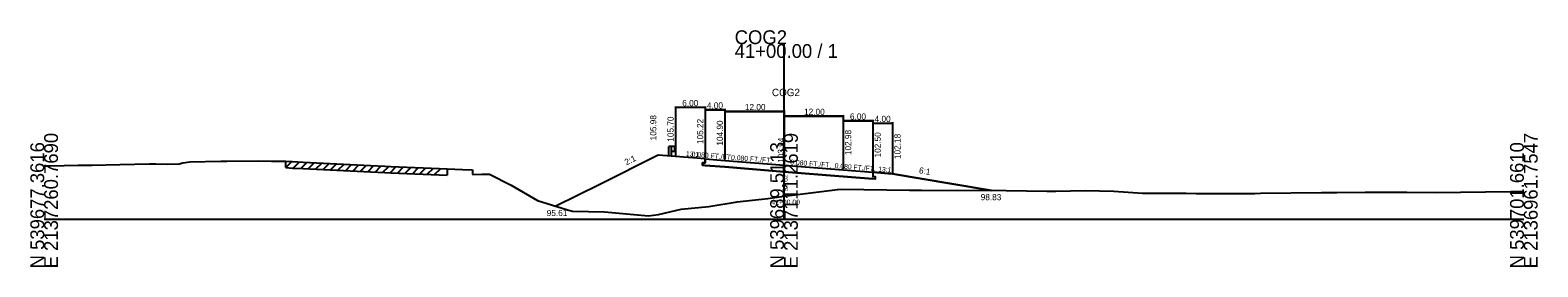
# Model space of a CAD drawing. Extents: x -13397 to 2303, y -10 to 39059.
# Drawn here: x 997.2 to 1302.8, y 21990.3 to 22038.3 of the extents above; entities that cross this region are included whole.
import ezdxf

# ---------------------------------------------------------------- set-up
doc = ezdxf.new("R2010")
doc.units = 0
for name, color, linetype in [('Level 1', 7, 'Continuous'), ('Level 5', 7, 'Continuous'), ('Level 53', 7, 'Continuous'), ('Level 54', 7, 'Continuous'), ('Level 55', 7, 'Continuous'), ('Level 7', 7, 'Continuous'), ('RD_GPK_XS_Cell', 7, 'Continuous'), ('RD_XS_EwShp', 7, 'Continuous'), ('RD_XS_ExGround', 7, 'Continuous'), ('RD_XS_ExPaveRet', 7, 'Continuous'), ('RD_XS_Pave', 7, 'Continuous'), ('RD_XS_TX_Baseline', 7, 'Continuous'), ('RD_XS_TX_Elev_EX', 7, 'Continuous'), ('RD_XS_TX_Elev_PR', 7, 'Continuous'), ('RD_XS_TX_Station', 7, 'Continuous')]:
    doc.layers.add(name, color=color, linetype=linetype)

msp = doc.modelspace()

# ---------------------------------------------------------------- linework, layer by layer
at = {"layer": 'Level 1'}
for p, q in [((1126.66, 22012.7), (1126.66, 22014.69)), ((1127.22, 22014.69), (1126.66, 22014.69)), ((1127.22, 22012.7), (1127.22, 22014.69)), ((1127.77, 22014.69), (1127.22, 22014.69)), ((1127.77, 22013.72), (1127.22, 22013.72)), ((1127.77, 22014.69), (1127.77, 22013.72)), ((1127.85, 22014.61), (1127.77, 22014.63)), ((1127.85, 22013.79), (1127.77, 22013.78)), ((1127.84, 22014.28), (1127.84, 22014.12)), ((1127.98, 22014.52), (1127.86, 22014.61)), ((1127.98, 22014.42), (1127.86, 22014.32)), ((1127.98, 22013.99), (1127.86, 22014.08)), ((1127.98, 22013.89), (1127.86, 22013.79))]:
    msp.add_line(p, q, dxfattribs=at)
for centre, radius, start, end in [((1127.91, 22014.28), 0.0651, 135, 180), ((1127.91, 22014.12), 0.0651, 180, 237.0105), ((1127.85, 22014.59), 0.026, 50.9495, 90), ((1127.85, 22013.81), 0.026, 270, 309.0504), ((1127.93, 22014.47), 0.0651, 309.0337, 50.9664), ((1127.93, 22013.94), 0.0651, 309.0337, 50.9664)]:
    msp.add_arc(centre, radius, start, end, dxfattribs=at)
at = {"layer": 'Level 5'}
for p, q in [((1134, 22012.22), (1134, 22011.39)), ((1133.5, 22011.43), (1133.5, 22010.93)), ((1134, 22011.39), (1133.5, 22011.43)), ((1133.5, 22010.93), (1134, 22010.89)), ((1138, 22010.57), (1134, 22010.89)), ((1138, 22010.57), (1134, 22010.89)), ((1138, 22010.57), (1134, 22010.89)), ((1134, 22010.89), (1138, 22010.57)), ((1150, 22009.61), (1138, 22010.57)), ((1150, 22009.61), (1138, 22010.57)), ((1150, 22009.61), (1138, 22010.57)), ((1138, 22010.57), (1150, 22009.61)), ((1138, 22010.57), (1150, 22009.61)), ((1162, 22008.65), (1150, 22009.61)), ((1162, 22008.65), (1150, 22009.61)), ((1150, 22009.61), (1162, 22008.65)), ((1150, 22009.61), (1162, 22008.65)), ((1150, 22009.61), (1162, 22008.65)), ((1168, 22009.5), (1168, 22008.67)), ((1168, 22008.17), (1162, 22008.65)), ((1162, 22008.65), (1168, 22008.17)), ((1162, 22008.65), (1168, 22008.17)), ((1162, 22008.65), (1168, 22008.17)), ((1168, 22008.67), (1168.5, 22008.63)), ((1168.5, 22008.13), (1168, 22008.17)), ((1168.5, 22008.63), (1168.5, 22008.13))]:
    msp.add_line(p, q, dxfattribs=at)
at = {"layer": 'Level 54'}
for p, q in [((1128, 22022.85), (1128, 22012.9)), ((1134, 22022.65), (1128, 22022.65)), ((1134, 22022.85), (1134, 22012.42)), ((1134, 22022.37), (1134, 22012.42)), ((1134, 22022.37), (1134, 22012.42)), ((1134, 22022.37), (1134, 22012.42)), ((1134, 22022.37), (1134, 22012.42)), ((1134, 22022.17), (1138, 22022.17)), ((1134, 22022.17), (1138, 22022.17)), ((1134, 22022.17), (1138, 22022.17)), ((1138, 22022.17), (1134, 22022.17)), ((1138, 22022.37), (1138, 22012.1)), ((1138, 22022.37), (1138, 22012.1)), ((1138, 22022.37), (1138, 22012.1)), ((1138, 22022.37), (1138, 22012.1)), ((1138, 22022.05), (1138, 22012.1)), ((1138, 22022.05), (1138, 22012.1)), ((1138, 22022.05), (1138, 22012.1)), ((1138, 22022.05), (1138, 22012.1)), ((1138, 22022.05), (1138, 22012.1)), ((1138, 22021.85), (1150, 22021.85)), ((1138, 22021.85), (1150, 22021.85)), ((1138, 22021.85), (1150, 22021.85)), ((1150, 22021.85), (1138, 22021.85)), ((1150, 22021.85), (1138, 22021.85)), ((1150, 22022.05), (1150, 22011.14)), ((1150, 22022.05), (1150, 22011.14)), ((1150, 22022.05), (1150, 22011.14)), ((1150, 22022.05), (1150, 22011.14)), ((1150, 22022.05), (1150, 22011.14)), ((1150, 22021.09), (1150, 22011.14)), ((1150, 22021.09), (1150, 22011.14)), ((1150, 22021.09), (1150, 22011.14)), ((1150, 22021.09), (1150, 22011.14)), ((1150, 22021.09), (1150, 22011.14)), ((1150, 22020.89), (1162, 22020.89)), ((1150, 22020.89), (1162, 22020.89)), ((1162, 22020.89), (1150, 22020.89)), ((1162, 22020.89), (1150, 22020.89)), ((1162, 22020.89), (1150, 22020.89)), ((1162, 22021.09), (1162, 22010.18)), ((1162, 22021.09), (1162, 22010.18)), ((1162, 22021.09), (1162, 22010.18)), ((1162, 22021.09), (1162, 22010.18)), ((1162, 22021.09), (1162, 22010.18)), ((1162, 22020.13), (1162, 22010.18)), ((1162, 22020.13), (1162, 22010.18)), ((1162, 22020.13), (1162, 22010.18)), ((1162, 22020.13), (1162, 22010.18)), ((1162, 22019.93), (1168, 22019.93)), ((1168, 22019.93), (1162, 22019.93)), ((1168, 22019.93), (1162, 22019.93)), ((1168, 22019.93), (1162, 22019.93)), ((1168, 22020.13), (1168, 22009.7)), ((1168, 22020.13), (1168, 22009.7)), ((1168, 22020.13), (1168, 22009.7)), ((1168, 22020.13), (1168, 22009.7)), ((1168, 22019.65), (1168, 22009.7)), ((1168, 22019.45), (1172, 22019.45)), ((1172, 22019.65), (1172, 22009.38))]:
    msp.add_line(p, q, dxfattribs=at)
at = {"layer": 'Level 7'}
for p, q in [((1124.5, 22012.98), (1112.5, 22006.98)), ((1128, 22012.7), (1124.5, 22012.98)), ((1134, 22012.22), (1128, 22012.7)), ((1168, 22009.5), (1172, 22009.18)), ((1172, 22009.18), (1184, 22007.18)), ((1112.5, 22006.98), (1103.77, 22002.61)), ((1184, 22007.18), (1192.08, 22005.83))]:
    msp.add_line(p, q, dxfattribs=at)
at = {"layer": 'RD_GPK_XS_Cell'}
for p, q in [((1150, 22000), (1150, 22035.49)), ((1000, 22000), (1150, 22000)), ((1150, 22000), (1300, 22000))]:
    msp.add_line(p, q, dxfattribs=at)
at = {"layer": 'RD_XS_EwShp'}
msp.add_lwpolyline([(1134, 22012.22), (1128, 22012.7), (1124.5, 22012.98), (1112.5, 22006.98), (1103.77, 22002.61), (1106.13, 22001.88), (1107.15, 22001.59), (1113.62, 22001.45), (1122.54, 22000.68), (1124.54, 22000.92), (1129.13, 22001.99), (1134.73, 22002.58), (1140.51, 22003.49), (1146.73, 22004.19), (1148.16, 22004.39), (1150, 22004.62), (1160.83, 22005.99), (1161.58, 22006.04), (1175.46, 22005.84), (1176.05, 22005.87), (1176.64, 22005.85), (1177.86, 22005.86), (1192.08, 22005.83), (1184, 22007.18), (1172, 22009.18), (1168, 22009.5), (1168, 22008.67), (1168.5, 22008.63), (1168.5, 22008.13), (1168, 22008.17), (1162, 22008.65), (1150, 22009.61), (1138, 22010.57), (1134, 22010.89), (1133.5, 22010.93), (1133.5, 22011.43), (1134, 22011.39)], close=True, dxfattribs=at)
at = {"layer": 'RD_XS_ExGround'}
for p, q in [((1000, 22010.79), (1001.19, 22010.82)), ((1001.19, 22010.82), (1006.9, 22010.91)), ((1006.9, 22010.91), (1008.29, 22010.93)), ((1008.29, 22010.93), (1009.7, 22010.96)), ((1009.7, 22010.96), (1015.33, 22011.05)), ((1015.33, 22011.05), (1021.36, 22011.21)), ((1021.36, 22011.21), (1022.65, 22011.23)), ((1022.65, 22011.23), (1025.05, 22011.17)), ((1025.05, 22011.17), (1027.36, 22011.18)), ((1027.36, 22011.18), (1028.13, 22011.39)), ((1028.13, 22011.39), (1029.51, 22011.63)), ((1029.51, 22011.63), (1035.83, 22011.76)), ((1035.83, 22011.76), (1037.06, 22011.77)), ((1037.06, 22011.77), (1043.55, 22011.83)), ((1043.55, 22011.83), (1046.1, 22011.78)), ((1046.1, 22011.78), (1049, 22011.73)), ((1049, 22011.73), (1050.34, 22011.65)), ((1050.34, 22011.65), (1052.49, 22011.54)), ((1052.49, 22011.54), (1066.18, 22010.87)), ((1066.18, 22010.87), (1069.08, 22010.73)), ((1069.08, 22010.73), (1070.28, 22010.69)), ((1070.28, 22010.69), (1081.73, 22010.22)), ((1081.73, 22010.22), (1084.81, 22010.08)), ((1084.81, 22010.08), (1086.84, 22010.01)), ((1086.84, 22010.01), (1086.84, 22009.07)), ((1086.84, 22009.07), (1088.75, 22009.1)), ((1088.75, 22009.1), (1090.32, 22009.09)), ((1090.32, 22009.09), (1094.67, 22006.91)), ((1094.67, 22006.91), (1100.03, 22003.77)), ((1160.83, 22005.99), (1161.58, 22006.04)), ((1161.58, 22006.04), (1175.46, 22005.84)), ((1100.03, 22003.77), (1106.13, 22001.88)), ((1134.73, 22002.58), (1140.51, 22003.49)), ((1140.51, 22003.49), (1146.73, 22004.19)), ((1146.73, 22004.19), (1148.16, 22004.39)), ((1148.16, 22004.39), (1150, 22004.62)), ((1150, 22004.62), (1160.83, 22005.99)), ((1175.46, 22005.84), (1176.05, 22005.87)), ((1176.05, 22005.87), (1176.64, 22005.85)), ((1176.64, 22005.85), (1177.86, 22005.86)), ((1177.86, 22005.86), (1195.01, 22005.83)), ((1195.01, 22005.83), (1203.28, 22005.67)), ((1203.28, 22005.67), (1205.11, 22005.69)), ((1205.11, 22005.69), (1211.03, 22005.78)), ((1211.03, 22005.78), (1216.85, 22005.68)), ((1216.85, 22005.68), (1222.66, 22005.25)), ((1222.66, 22005.25), (1231.54, 22005.23)), ((1231.54, 22005.23), (1233.58, 22005.2)), ((1233.58, 22005.2), (1239.61, 22005.17)), ((1239.61, 22005.17), (1245.44, 22005.22)), ((1245.44, 22005.22), (1246.61, 22005.25)), ((1246.61, 22005.25), (1259, 22005.37)), ((1259, 22005.37), (1262.06, 22005.41)), ((1262.06, 22005.41), (1267.85, 22005.45)), ((1267.85, 22005.45), (1276.3, 22005.46)), ((1276.3, 22005.46), (1281.99, 22005.41)), ((1281.99, 22005.41), (1297.33, 22005.61)), ((1297.33, 22005.61), (1300, 22005.61)), ((1106.13, 22001.88), (1107.15, 22001.59)), ((1107.15, 22001.59), (1113.62, 22001.45)), ((1113.62, 22001.45), (1122.54, 22000.68)), ((1122.54, 22000.68), (1124.54, 22000.92)), ((1124.54, 22000.92), (1129.13, 22001.99)), ((1129.13, 22001.99), (1134.73, 22002.58))]:
    msp.add_line(p, q, dxfattribs=at)
at = {"layer": 'RD_XS_ExPaveRet'}
for p, q in [((1049, 22010.43), (1049, 22011.73)), ((1049, 22010.43), (1050.24, 22011.66)), ((1049, 22010.43), (1050.34, 22010.35)), ((1050.34, 22010.35), (1052.49, 22010.24)), ((1050.51, 22010.34), (1051.75, 22011.58)), ((1052.01, 22010.27), (1053.26, 22011.51)), ((1052.49, 22010.24), (1066.18, 22009.57)), ((1053.52, 22010.19), (1054.77, 22011.43)), ((1055.03, 22010.12), (1056.28, 22011.36)), ((1056.54, 22010.04), (1057.79, 22011.28)), ((1058.05, 22009.97), (1059.3, 22011.21)), ((1059.56, 22009.9), (1060.8, 22011.13)), ((1061.07, 22009.82), (1062.31, 22011.06)), ((1062.58, 22009.75), (1063.82, 22010.98)), ((1064.08, 22009.67), (1065.33, 22010.91)), ((1065.59, 22009.6), (1066.84, 22010.84)), ((1066.18, 22009.57), (1069.08, 22009.43)), ((1067.1, 22009.52), (1068.35, 22010.77)), ((1068.61, 22009.45), (1069.87, 22010.7)), ((1069.08, 22009.43), (1070.28, 22009.39)), ((1070.12, 22009.39), (1071.38, 22010.64)), ((1070.28, 22009.39), (1081.73, 22008.92)), ((1071.63, 22009.33), (1072.88, 22010.58)), ((1073.14, 22009.27), (1074.39, 22010.52)), ((1074.65, 22009.21), (1075.9, 22010.46)), ((1076.15, 22009.15), (1077.41, 22010.4)), ((1077.66, 22009.09), (1078.92, 22010.34)), ((1079.17, 22009.03), (1080.43, 22010.28)), ((1081.73, 22010.22), (1081.73, 22008.92))]:
    msp.add_line(p, q, dxfattribs=at)
at = {"layer": 'RD_XS_Pave'}
for p, q in [((1134, 22012.22), (1138, 22011.9)), ((1138, 22011.9), (1150, 22010.94)), ((1150, 22010.94), (1162, 22009.98)), ((1162, 22009.98), (1168, 22009.5))]:
    msp.add_line(p, q, dxfattribs=at)

# ---------------------------------------------------------------- texts
at = {"layer": 'Level 53'}
for s, rotation, p in [('105.98', 90, (1124.12, 22015.98)), ('105.70', 90, (1127.62, 22015.7)), ('105.22', 90, (1133.62, 22015.22)), ('104.90', 90, (1137.62, 22014.9)), ('104.90', 90, (1137.62, 22014.9)), ('104.90', 90, (1137.62, 22014.9)), ('102.98', 90, (1163.62, 22012.98)), ('102.98', 90, (1163.62, 22012.98)), ('102.98', 90, (1163.62, 22012.98)), ('102.50', 90, (1169.62, 22012.5)), ('102.18', 90, (1173.62, 22012.18)), ('2:1', 26.5651, (1118.05, 22010.87)), ('6:1', 350.5377, (1177.3, 22009.31))]:
    msp.add_text(s, height=1.25, rotation=rotation, dxfattribs=at).set_placement(p)
for s, p in [('98.83', (1189.88, 22003.83)), ('95.61', (1101.89, 22000.61))]:
    msp.add_text(s, height=1.25, dxfattribs=at).set_placement(p)
at = {"layer": 'Level 54'}
for s, p in [('6.00', (1129.37, 22022.9)), ('4.00', (1134.37, 22022.42)), ('4.00', (1134.37, 22022.42)), ('4.00', (1134.37, 22022.42)), ('4.00', (1134.37, 22022.42)), ('12.00', (1142.07, 22022.1)), ('12.00', (1142.07, 22022.1)), ('12.00', (1142.07, 22022.1)), ('12.00', (1142.07, 22022.1)), ('12.00', (1142.07, 22022.1)), ('12.00', (1154.07, 22021.14)), ('12.00', (1154.07, 22021.14)), ('12.00', (1154.07, 22021.14)), ('12.00', (1154.07, 22021.14)), ('12.00', (1154.07, 22021.14)), ('6.00', (1163.37, 22020.18)), ('6.00', (1163.37, 22020.18)), ('6.00', (1163.37, 22020.18)), ('6.00', (1163.37, 22020.18)), ('4.00', (1168.37, 22019.7))]:
    msp.add_text(s, height=1.25, dxfattribs=at).set_placement(p)
at = {"layer": 'Level 55'}
for s, p in [('13:1', (1130.07, 22012.79)), ('0.080 FT./FT.', (1131.24, 22012.69)), ('0.080 FT./FT.', (1131.24, 22012.69)), ('0.080 FT./FT.', (1131.24, 22012.69)), ('0.080 FT./FT.', (1131.24, 22012.69)), ('0.080 FT./FT.', (1139.24, 22012.05)), ('0.080 FT./FT.', (1139.24, 22012.05)), ('0.080 FT./FT.', (1139.24, 22012.05)), ('0.080 FT./FT.', (1139.24, 22012.05)), ('0.080 FT./FT.', (1139.24, 22012.05)), ('0.080 FT./FT.', (1151.24, 22011.09)), ('0.080 FT./FT.', (1151.24, 22011.09)), ('0.080 FT./FT.', (1151.24, 22011.09)), ('0.080 FT./FT.', (1151.24, 22011.09)), ('0.080 FT./FT.', (1151.24, 22011.09)), ('0.080 FT./FT.', (1160.24, 22010.37)), ('0.080 FT./FT.', (1160.24, 22010.37)), ('0.080 FT./FT.', (1160.24, 22010.37)), ('0.080 FT./FT.', (1160.24, 22010.37)), ('13:1', (1169.07, 22009.67))]:
    msp.add_text(s, height=1, rotation=355.4261, dxfattribs=at).set_placement(p)
at = {"layer": 'RD_GPK_XS_Cell'}
for s, p in [('COG2', (1140, 22035.49)), ('41+00.00 / 1', (1140, 22032.69))]:
    msp.add_text(s, height=2.8, dxfattribs=at).set_placement(p)
for s, p in [('N 539677.3616', (1000, 21990)), ('E 2137260.7690', (1002.8, 21990)), ('N 539689.5113', (1150, 21990)), ('E 2137111.2619', (1152.8, 21990)), ('N 539701.6610', (1300, 21990)), ('E 2136961.7547', (1302.8, 21990))]:
    msp.add_text(s, height=2.8, rotation=90, dxfattribs=at).set_placement(p)
at = {"layer": 'RD_XS_TX_Baseline'}
msp.add_text('COG2', height=1.5, dxfattribs=at).set_placement((1147.55, 22024.94))
at = {"layer": 'RD_XS_TX_Elev_EX'}
msp.add_text('97.62', height=1, rotation=90, dxfattribs=at).set_placement((1150.75, 22005.62))
at = {"layer": 'RD_XS_TX_Elev_PR'}
msp.add_text(' 103.94', height=1.25, rotation=90, dxfattribs=at).set_placement((1150, 22010.94))
at = {"layer": 'RD_XS_TX_Station'}
msp.add_text('41+00.00', height=1, dxfattribs=at).set_placement((1147.43, 22002.94))

doc.saveas('drawing.dxf')
